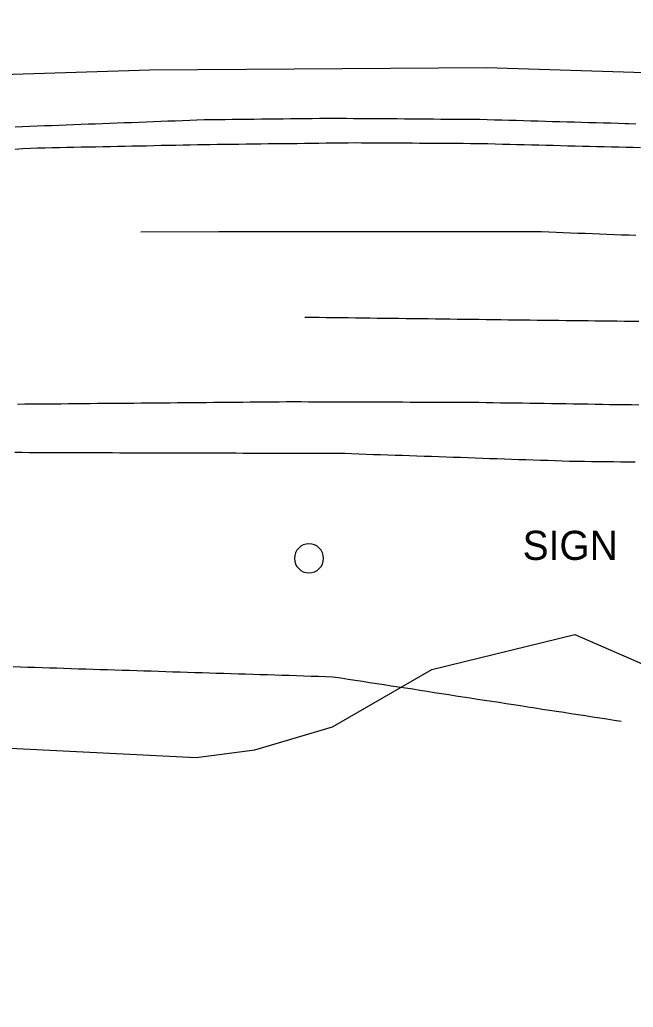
# Model space of a CAD drawing. Extents: x 1901471 to 1963503, y 756461 to 799997.
# Drawn here: x 1929238.5 to 1929322.9, y 772605.7 to 772741.4 of the extents above; entities that cross this region are included whole.
import ezdxf

# ---------------------------------------------------------------- set-up
doc = ezdxf.new("R2010")
doc.units = 0
for name, color, linetype in [('Default', 7, 'Continuous'), ('RD_EX_GuardRail', 7, 'Continuous'), ('RD_EX_H2O', 7, 'Continuous'), ('RD_EX_Road', 7, 'Continuous'), ('RD_EX_UT', 7, 'Continuous'), ('RD_EX_VEG', 7, 'Continuous'), ('RD_HC_Cl', 7, 'Continuous')]:
    doc.layers.add(name, color=color, linetype=linetype)

# ---------------------------------------------------------------- blocks, each defined once
blk = doc.blocks.new('OP')
at = {"layer": 'Default'}
for start, end in [(90, 270), (270, 90)]:
    blk.add_arc((0, 0), 0.127, start, end, dxfattribs=at)

msp = doc.modelspace()

# ---------------------------------------------------------------- linework, layer by layer
at = {"layer": 'RD_EX_GuardRail'}
msp.add_lwpolyline([(1929474.41, 772727.1), (1929451.68, 772728.36), (1929414.45, 772730.43), (1929363.47, 772732.92), (1929302.7, 772734.83), (1929256.4, 772734.53), (1929220.15, 772733.36), (1929183.59, 772730.94), (1929148.14, 772728.16), (1929110.76, 772724.01), (1929078.24, 772720), (1929049.58, 772715.78), (1929018.26, 772709.47), (1928983.73, 772702.41), (1928948.59, 772694.52), (1928918.73, 772687.07), (1928901.27, 772682.37)], dxfattribs=at)
at = {"layer": 'RD_EX_H2O'}
msp.add_lwpolyline([(1929237.62, 772652.56), (1929238.62, 772652.53), (1929239.62, 772652.5), (1929240.62, 772652.46), (1929241.62, 772652.43), (1929242.62, 772652.4), (1929243.62, 772652.37), (1929244.62, 772652.34), (1929245.61, 772652.31), (1929246.61, 772652.27), (1929247.61, 772652.24), (1929248.61, 772652.21), (1929249.61, 772652.18), (1929250.61, 772652.15), (1929251.61, 772652.12), (1929252.61, 772652.09), (1929253.61, 772652.05), (1929254.61, 772652.02), (1929255.6, 772651.99), (1929255.6, 772651.99), (1929256.6, 772651.96), (1929257.6, 772651.93), (1929258.6, 772651.9), (1929259.6, 772651.86), (1929260.6, 772651.83), (1929261.6, 772651.8), (1929262.6, 772651.77), (1929263.6, 772651.74), (1929264.6, 772651.71), (1929265.59, 772651.67), (1929266.59, 772651.64), (1929267.59, 772651.61), (1929268.59, 772651.58), (1929269.59, 772651.55), (1929270.59, 772651.52), (1929271.59, 772651.48), (1929272.59, 772651.45), (1929273.59, 772651.42), (1929274.58, 772651.39), (1929275.58, 772651.36), (1929276.58, 772651.33), (1929277.58, 772651.29), (1929278.58, 772651.26), (1929279.58, 772651.23), (1929280.58, 772651.2), (1929281.58, 772651.17), (1929282.68, 772651), (1929283.67, 772650.85), (1929284.65, 772650.69), (1929285.64, 772650.54), (1929286.63, 772650.39), (1929287.62, 772650.24), (1929288.61, 772650.08), (1929289.6, 772649.93), (1929290.58, 772649.78), (1929291.57, 772649.63), (1929292.56, 772649.48), (1929293.55, 772649.32), (1929294.54, 772649.17), (1929295.52, 772649.02), (1929296.51, 772648.87), (1929297.5, 772648.71), (1929298.49, 772648.56), (1929300.47, 772648.26), (1929301.45, 772648.1), (1929302.44, 772647.95), (1929303.43, 772647.8), (1929304.42, 772647.65), (1929305.41, 772647.5), (1929306.4, 772647.34), (1929307.38, 772647.19), (1929308.37, 772647.04), (1929309.36, 772646.89), (1929310.35, 772646.73), (1929311.34, 772646.58), (1929312.33, 772646.43), (1929313.31, 772646.28), (1929314.3, 772646.12), (1929316.28, 772645.82), (1929317.27, 772645.67), (1929318.26, 772645.52), (1929319.24, 772645.36), (1929320.23, 772645.21), (1929321.22, 772645.06)], dxfattribs=at)
at = {"layer": 'RD_EX_Road'}
for points in [[(1929323.21, 772727.11), (1929322.21, 772727.15), (1929321.77, 772727.16), (1929320.77, 772727.19), (1929319.77, 772727.22), (1929318.77, 772727.24), (1929317.77, 772727.27), (1929316.77, 772727.3), (1929315.77, 772727.33), (1929314.78, 772727.35), (1929313.78, 772727.38), (1929312.78, 772727.41), (1929311.78, 772727.44), (1929310.78, 772727.47), (1929309.78, 772727.49), (1929308.78, 772727.52), (1929307.78, 772727.55), (1929306.78, 772727.58), (1929305.78, 772727.61), (1929304.79, 772727.63), (1929303.79, 772727.66), (1929302.79, 772727.69), (1929301.79, 772727.72), (1929301.41, 772727.73), (1929300.41, 772727.73), (1929299.41, 772727.74), (1929298.41, 772727.75), (1929297.41, 772727.76), (1929296.42, 772727.76), (1929295.42, 772727.77), (1929294.42, 772727.78), (1929293.42, 772727.78), (1929292.42, 772727.79), (1929291.42, 772727.8), (1929290.42, 772727.81), (1929289.42, 772727.81), (1929288.42, 772727.82), (1929287.42, 772727.83), (1929286.42, 772727.83), (1929285.42, 772727.84), (1929284.42, 772727.85), (1929283.42, 772727.86), (1929282.42, 772727.86), (1929281.42, 772727.87), (1929280.75, 772727.87), (1929279.75, 772727.86), (1929278.75, 772727.85), (1929277.75, 772727.84), (1929276.75, 772727.83), (1929275.75, 772727.82), (1929274.75, 772727.8), (1929273.75, 772727.79), (1929272.75, 772727.78), (1929271.75, 772727.77), (1929270.75, 772727.76), (1929269.75, 772727.75), (1929268.75, 772727.73), (1929267.75, 772727.72), (1929266.75, 772727.71), (1929265.75, 772727.7), (1929264.75, 772727.69), (1929263.9, 772727.68), (1929262.9, 772727.64), (1929261.9, 772727.6), (1929260.9, 772727.57), (1929259.91, 772727.53), (1929258.91, 772727.49), (1929257.91, 772727.45), (1929256.91, 772727.42), (1929255.91, 772727.38), (1929254.91, 772727.34), (1929253.91, 772727.3), (1929252.91, 772727.27), (1929251.91, 772727.23), (1929250.92, 772727.19), (1929249.92, 772727.15), (1929248.92, 772727.11), (1929247.92, 772727.08), (1929246.92, 772727.04), (1929245.92, 772727), (1929244.92, 772726.96), (1929243.92, 772726.93), (1929242.92, 772726.89), (1929241.93, 772726.85), (1929240.93, 772726.81), (1929239.93, 772726.78), (1929238.93, 772726.74), (1929237.93, 772726.7)], [(1929237.93, 772723.68), (1929238.93, 772723.74), (1929239.99, 772723.81), (1929240.99, 772723.83), (1929241.99, 772723.86), (1929242.99, 772723.88), (1929243.99, 772723.9), (1929244.99, 772723.92), (1929245.99, 772723.94), (1929246.99, 772723.96), (1929247.99, 772723.98), (1929248.99, 772724), (1929249.99, 772724.02), (1929250.99, 772724.04), (1929251.99, 772724.06), (1929252.99, 772724.08), (1929253.99, 772724.1), (1929254.99, 772724.12), (1929255.98, 772724.14), (1929256.98, 772724.16), (1929257.98, 772724.19), (1929258.98, 772724.21), (1929259.98, 772724.23), (1929260.98, 772724.25), (1929261.98, 772724.27), (1929262.98, 772724.29), (1929263.98, 772724.31), (1929264.2, 772724.31), (1929264.67, 772724.32), (1929265.67, 772724.33), (1929266.67, 772724.34), (1929267.67, 772724.36), (1929268.67, 772724.37), (1929269.67, 772724.38), (1929270.67, 772724.39), (1929271.67, 772724.4), (1929272.67, 772724.42), (1929273.67, 772724.43), (1929274.67, 772724.44), (1929275.66, 772724.45), (1929276.66, 772724.46), (1929277.66, 772724.48), (1929278.66, 772724.49), (1929279.66, 772724.5), (1929280.66, 772724.51), (1929281.66, 772724.52), (1929282.66, 772724.54), (1929283.66, 772724.55), (1929284.66, 772724.56), (1929285.51, 772724.55), (1929286.51, 772724.55), (1929287.51, 772724.54), (1929288.51, 772724.54), (1929289.51, 772724.53), (1929290.5, 772724.52), (1929291.5, 772724.52), (1929292.5, 772724.51), (1929293.5, 772724.5), (1929294.5, 772724.5), (1929295.5, 772724.49), (1929296.5, 772724.48), (1929297.5, 772724.48), (1929298.5, 772724.47), (1929299.5, 772724.47), (1929300.5, 772724.46), (1929301.5, 772724.45), (1929301.88, 772724.44), (1929302.88, 772724.42), (1929303.88, 772724.39), (1929304.88, 772724.37), (1929305.88, 772724.34), (1929306.87, 772724.32), (1929307.87, 772724.29), (1929308.87, 772724.27), (1929309.87, 772724.24), (1929310.87, 772724.22), (1929311.87, 772724.19), (1929312.87, 772724.17), (1929313.87, 772724.14), (1929314.87, 772724.12), (1929315.87, 772724.09), (1929316.87, 772724.07), (1929317.87, 772724.04), (1929318.87, 772724.02), (1929319.87, 772723.99), (1929320.87, 772723.97), (1929321.87, 772723.94), (1929322.86, 772723.92), (1929323.86, 772723.89)], [(1929255.16, 772712.29), (1929265.89, 772712.33), (1929266.89, 772712.33), (1929267.89, 772712.33), (1929268.89, 772712.33), (1929269.89, 772712.33), (1929270.89, 772712.33), (1929271.88, 772712.33), (1929272.88, 772712.33), (1929273.88, 772712.33), (1929274.88, 772712.33), (1929275.88, 772712.33), (1929276.88, 772712.34), (1929277.88, 772712.34), (1929278.88, 772712.34), (1929279.88, 772712.34), (1929280.88, 772712.34), (1929281.88, 772712.34), (1929282.88, 772712.34), (1929283.88, 772712.34), (1929284.88, 772712.34), (1929285.88, 772712.34), (1929286.88, 772712.34), (1929287.88, 772712.35), (1929288.88, 772712.35), (1929289.88, 772712.35), (1929290.88, 772712.35), (1929291.88, 772712.35), (1929292.88, 772712.35), (1929293.88, 772712.35), (1929294.88, 772712.35), (1929295.88, 772712.35), (1929296.87, 772712.35), (1929297.87, 772712.35), (1929298.87, 772712.35), (1929299.87, 772712.36), (1929300.87, 772712.36), (1929301.87, 772712.36), (1929302.87, 772712.36), (1929303.87, 772712.36), (1929304.87, 772712.36), (1929305.87, 772712.36), (1929306.87, 772712.36), (1929307.87, 772712.36), (1929308.87, 772712.36), (1929309.26, 772712.36), (1929310.26, 772712.33), (1929311.26, 772712.29), (1929312.26, 772712.25), (1929313.25, 772712.21), (1929314.25, 772712.17), (1929315.25, 772712.14), (1929316.25, 772712.1), (1929317.25, 772712.06), (1929318.25, 772712.02), (1929319.25, 772711.98), (1929320.25, 772711.95), (1929321.25, 772711.91), (1929322.24, 772711.87), (1929323.24, 772711.83)], [(1929277.7, 772700.59), (1929278.67, 772700.57), (1929279.67, 772700.56), (1929280.67, 772700.55), (1929281.67, 772700.54), (1929282.67, 772700.52), (1929283.67, 772700.51), (1929284.67, 772700.5), (1929285.67, 772700.49), (1929286.67, 772700.47), (1929287.67, 772700.46), (1929288.66, 772700.45), (1929289.66, 772700.44), (1929290.66, 772700.42), (1929291.66, 772700.41), (1929292.66, 772700.4), (1929293.66, 772700.39), (1929294.66, 772700.37), (1929295.66, 772700.36), (1929296.66, 772700.35), (1929297.66, 772700.34), (1929298.66, 772700.32), (1929299.66, 772700.31), (1929300.66, 772700.3), (1929301.66, 772700.29), (1929302.66, 772700.27), (1929303.66, 772700.26), (1929304.65, 772700.25), (1929305.65, 772700.23), (1929306.65, 772700.22), (1929307.65, 772700.21), (1929308.65, 772700.2), (1929309.65, 772700.18), (1929309.65, 772700.18), (1929310.65, 772700.17), (1929311.65, 772700.16), (1929312.65, 772700.15), (1929313.65, 772700.13), (1929314.65, 772700.12), (1929315.65, 772700.11), (1929316.65, 772700.1), (1929317.65, 772700.08), (1929318.65, 772700.07), (1929319.65, 772700.06), (1929320.64, 772700.05), (1929321.64, 772700.03), (1929322.64, 772700.02), (1929323.64, 772700.01)], [(1929323.62, 772688.49), (1929322.62, 772688.51), (1929321.62, 772688.52), (1929320.62, 772688.54), (1929319.62, 772688.55), (1929318.62, 772688.57), (1929317.62, 772688.58), (1929316.62, 772688.6), (1929315.62, 772688.61), (1929314.62, 772688.63), (1929313.62, 772688.65), (1929312.62, 772688.66), (1929311.62, 772688.68), (1929310.62, 772688.69), (1929309.63, 772688.71), (1929308.63, 772688.72), (1929307.63, 772688.74), (1929306.63, 772688.75), (1929305.63, 772688.77), (1929304.63, 772688.78), (1929303.63, 772688.8), (1929302.63, 772688.82), (1929301.63, 772688.83), (1929300.63, 772688.85), (1929300.2, 772688.85), (1929299.2, 772688.85), (1929298.2, 772688.85), (1929297.2, 772688.86), (1929296.2, 772688.86), (1929295.2, 772688.86), (1929294.2, 772688.87), (1929293.2, 772688.87), (1929292.2, 772688.87), (1929291.2, 772688.88), (1929290.2, 772688.88), (1929289.21, 772688.88), (1929288.21, 772688.88), (1929287.21, 772688.89), (1929286.21, 772688.89), (1929285.21, 772688.89), (1929284.21, 772688.9), (1929283.21, 772688.9), (1929282.21, 772688.9), (1929281.21, 772688.91), (1929280.21, 772688.91), (1929279.21, 772688.91), (1929278.21, 772688.91), (1929277.21, 772688.92), (1929276.21, 772688.92), (1929275.21, 772688.92), (1929274.21, 772688.91), (1929273.21, 772688.91), (1929272.21, 772688.9), (1929271.21, 772688.89), (1929270.21, 772688.88), (1929269.21, 772688.87), (1929268.21, 772688.86), (1929267.21, 772688.85), (1929266.21, 772688.84), (1929265.21, 772688.83), (1929264.21, 772688.82), (1929263.21, 772688.81), (1929262.21, 772688.81), (1929261.21, 772688.8), (1929260.21, 772688.79), (1929259.21, 772688.78), (1929258.21, 772688.77), (1929257.21, 772688.76), (1929256.22, 772688.75), (1929255.22, 772688.74), (1929254.22, 772688.73), (1929253.22, 772688.72), (1929252.22, 772688.72), (1929251.22, 772688.71), (1929250.22, 772688.7), (1929249.22, 772688.69), (1929248.22, 772688.68), (1929247.22, 772688.67), (1929246.22, 772688.66), (1929245.22, 772688.65), (1929244.22, 772688.64), (1929243.22, 772688.63), (1929242.22, 772688.62), (1929241.22, 772688.62), (1929240.22, 772688.61), (1929239.22, 772688.6), (1929238.22, 772688.59)], [(1929323.14, 772680.64), (1929322.14, 772680.65), (1929321.14, 772680.66), (1929320.14, 772680.68), (1929319.14, 772680.69), (1929318.14, 772680.7), (1929317.14, 772680.71), (1929316.14, 772680.73), (1929315.14, 772680.74), (1929314.11, 772680.75), (1929313.11, 772680.79), (1929312.11, 772680.82), (1929311.11, 772680.86), (1929310.11, 772680.89), (1929309.11, 772680.92), (1929308.11, 772680.96), (1929307.11, 772680.99), (1929306.12, 772681.03), (1929305.12, 772681.06), (1929304.12, 772681.1), (1929303.12, 772681.13), (1929302.12, 772681.17), (1929301.12, 772681.2), (1929300.12, 772681.24), (1929299.12, 772681.27), (1929298.12, 772681.3), (1929297.13, 772681.34), (1929296.13, 772681.37), (1929295.13, 772681.41), (1929294.13, 772681.44), (1929293.13, 772681.48), (1929292.13, 772681.51), (1929291.13, 772681.55), (1929290.13, 772681.58), (1929289.13, 772681.62), (1929288.14, 772681.65), (1929287.14, 772681.68), (1929286.14, 772681.72), (1929285.14, 772681.75), (1929284.14, 772681.79), (1929283.25, 772681.82), (1929282.25, 772681.82), (1929281.25, 772681.82), (1929280.26, 772681.83), (1929279.26, 772681.83), (1929278.26, 772681.83), (1929277.26, 772681.84), (1929276.26, 772681.84), (1929275.26, 772681.84), (1929274.26, 772681.85), (1929273.26, 772681.85), (1929272.26, 772681.85), (1929271.26, 772681.86), (1929270.26, 772681.86), (1929269.26, 772681.86), (1929268.26, 772681.87), (1929267.27, 772681.87), (1929266.27, 772681.87), (1929265.27, 772681.87), (1929264.27, 772681.88), (1929263.27, 772681.88), (1929262.27, 772681.88), (1929261.27, 772681.89), (1929260.27, 772681.89), (1929259.27, 772681.89), (1929258.27, 772681.9), (1929257.27, 772681.9), (1929256.27, 772681.9), (1929255.28, 772681.91), (1929254.28, 772681.91), (1929253.28, 772681.91), (1929252.28, 772681.91), (1929251.28, 772681.92), (1929250.28, 772681.92), (1929249.28, 772681.92), (1929248.28, 772681.93), (1929247.28, 772681.93), (1929246.28, 772681.93), (1929245.28, 772681.94), (1929244.28, 772681.94), (1929243.28, 772681.94), (1929242.29, 772681.95), (1929241.29, 772681.95), (1929240.29, 772681.95), (1929239.85, 772681.95), (1929238.85, 772681.96), (1929237.85, 772681.96)]]:
    msp.add_lwpolyline(points, dxfattribs=at)
at = {"layer": 'RD_EX_VEG'}
msp.add_lwpolyline([(1929234.45, 772641.48), (1929262.77, 772640.06), (1929270.86, 772641.13), (1929281.54, 772644.26), (1929295.19, 772652.18), (1929314.85, 772656.98), (1929326.19, 772652.03), (1929338.68, 772640.68), (1929349.99, 772648.02), (1929371.32, 772650.75), (1929402.27, 772646.81), (1929423.65, 772647.67), (1929446.77, 772648.02), (1929465.63, 772640.03), (1929478.24, 772629.24), (1929484.93, 772613.91), (1929498.07, 772606.58), (1929509.69, 772598.32)], dxfattribs=at)
at = {"layer": 'RD_HC_Cl'}
for centre, radius, start, end in [((1933934.02, 762479.74), 11482.38, 112.01316, 122.84589), ((1933920.67, 762509.14), 11420.5, 112.014247, 122.846378), ((1933910.03, 762523.4), 11373.86, 112.013249, 123.541888)]:
    msp.add_arc(centre, radius, start, end, dxfattribs=at)

# ---------------------------------------------------------------- block references
at = {"layer": 'RD_EX_UT', "xscale": 15.748031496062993, "yscale": 15.748031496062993}
msp.add_blockref('OP', (1929278.29, 772667.43), dxfattribs=at)

# ---------------------------------------------------------------- texts
at = {"layer": 'RD_EX_Road'}
msp.add_text('SIGN', height=4, dxfattribs=at).set_placement((1929307.66, 772667.22))

doc.saveas('drawing.dxf')
